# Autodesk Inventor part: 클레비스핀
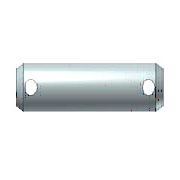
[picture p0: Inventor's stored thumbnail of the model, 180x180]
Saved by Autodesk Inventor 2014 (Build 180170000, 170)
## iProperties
IsCustomPart: 1
Created: 2012-02
Part Number: 클레비스핀
Material: 강철
Description: 머리가 없는 클레비스 핀 B
Document SubType Name: Modeling
Standard: ISO 2340
Designer: mduedu
Standard Revision: Second edition 1986-11-01
Standards Organization: ISO
Language: ko-KR
Size Designation: B - 8 x 45
Categories: <MemberInstance><Categories><Category DisplayName="조임쇠" InternalName="e4da775c-781d-43d5-af7c-5136215cf5a6" Mnemonic="FSTN"><Category DisplayName="핀" InternalNa
Density: 7.85 g/cm^3
Appearance: 강철
Author: mduedu
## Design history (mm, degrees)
sketch "스케치1"
  geometry: L1 (-4.5, 0)-(-4.5, 4); L2 (-4.5, 4)-(40.5, 4); L3 (40.5, 4)-(40.5, 0); L4 (-4.5, 0)-(40.5, 0); L5 (0, -1.46)-(0, 3.16) reference; L6 (-6.4, 0)-(18.8, 0) reference; C1 r 1 at (-1, 0); C2 r 1 at (37, 0)
  constraints: 8 end point, 2 centre point, 2 perpendicular, 2 point on line, 1 collinear, 1 parallel, 1 tangent, 1 vertical
  dimensions: "d0" = 8 diameter of L2 L4 (= NND); "d1" = 45 distance of L1.end L2.end (= NLG); "d2" = 3.5 distance from line of L1 C1.centre (= DIST1); "d3" = 3.5 distance from line of L3 C2.centre (= DIST2); "d4" = 2 diameter of C1 (= BOR1); "d5" = 2 diameter of C2 (= BOR2)
revolve "본체" stored, may be unused: angle "d7" = 90 deg
extrude "구멍1" cut sketch "스케치1" taper "d6" = 0 deg; stored distance "d8" = 10
extrude "구멍2" cut sketch "스케치1" taper "d13" = 0 deg; stored distance "d14" = 10
workaxis "Work Axis1"
workaxis "Work Axis2"
workplane "Work Plane1"
node "작업 평면5"
node "작업 평면6"
body "Solid1"
chamfer "모따기2" distance "d9" = 2 (= PHH2); stored, may be unused: angle "d10" = 30 deg (= FAWI2), second distance "d40" = 2 (= PHH2)
chamfer "모따기1" distance "d11" = 2 (= PHH1); stored, may be unused: angle "d12" = 30 deg (= FAWI1), second distance "d41" = 2 (= PHH1)
other parameters: "NLG" = 45 [user parameter; used in 1 equation term], "NND" = 8 [user parameter; used in 1 equation term], "PHH1" = 2 [user parameter; used in 3 equation terms], "PHH2" = 2 (= PHH1) [user parameter; used in 2 equation terms], "FAWI1" = 30 deg [user parameter; used in 1 equation term], "FAWI2" = 30 deg [user parameter; used in 1 equation term], "DIST1" = 3.5 [user parameter; used in 4 equation terms], "DIST2" = 3.5 (= DIST1) [user parameter; used in 1 equation term], "BOR1" = 2 [user parameter; used in 4 equation terms], "BOR2" = 2 (= BOR1) [user parameter; used in 1 equation term], "d15" = 0, "d42" = 0, "d43" = 0, "d44" = -4.5 (= -0.5 x BOR1 - DIST1), "d45" = -4.5 (= -0.5 x BOR1 - DIST1), "d47" = 0, "d48" = 0, "d49" = 0, "d50" = 0, "d51" = 0, "d52" = 0
